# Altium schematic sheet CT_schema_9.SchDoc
size 297 x 239 mm
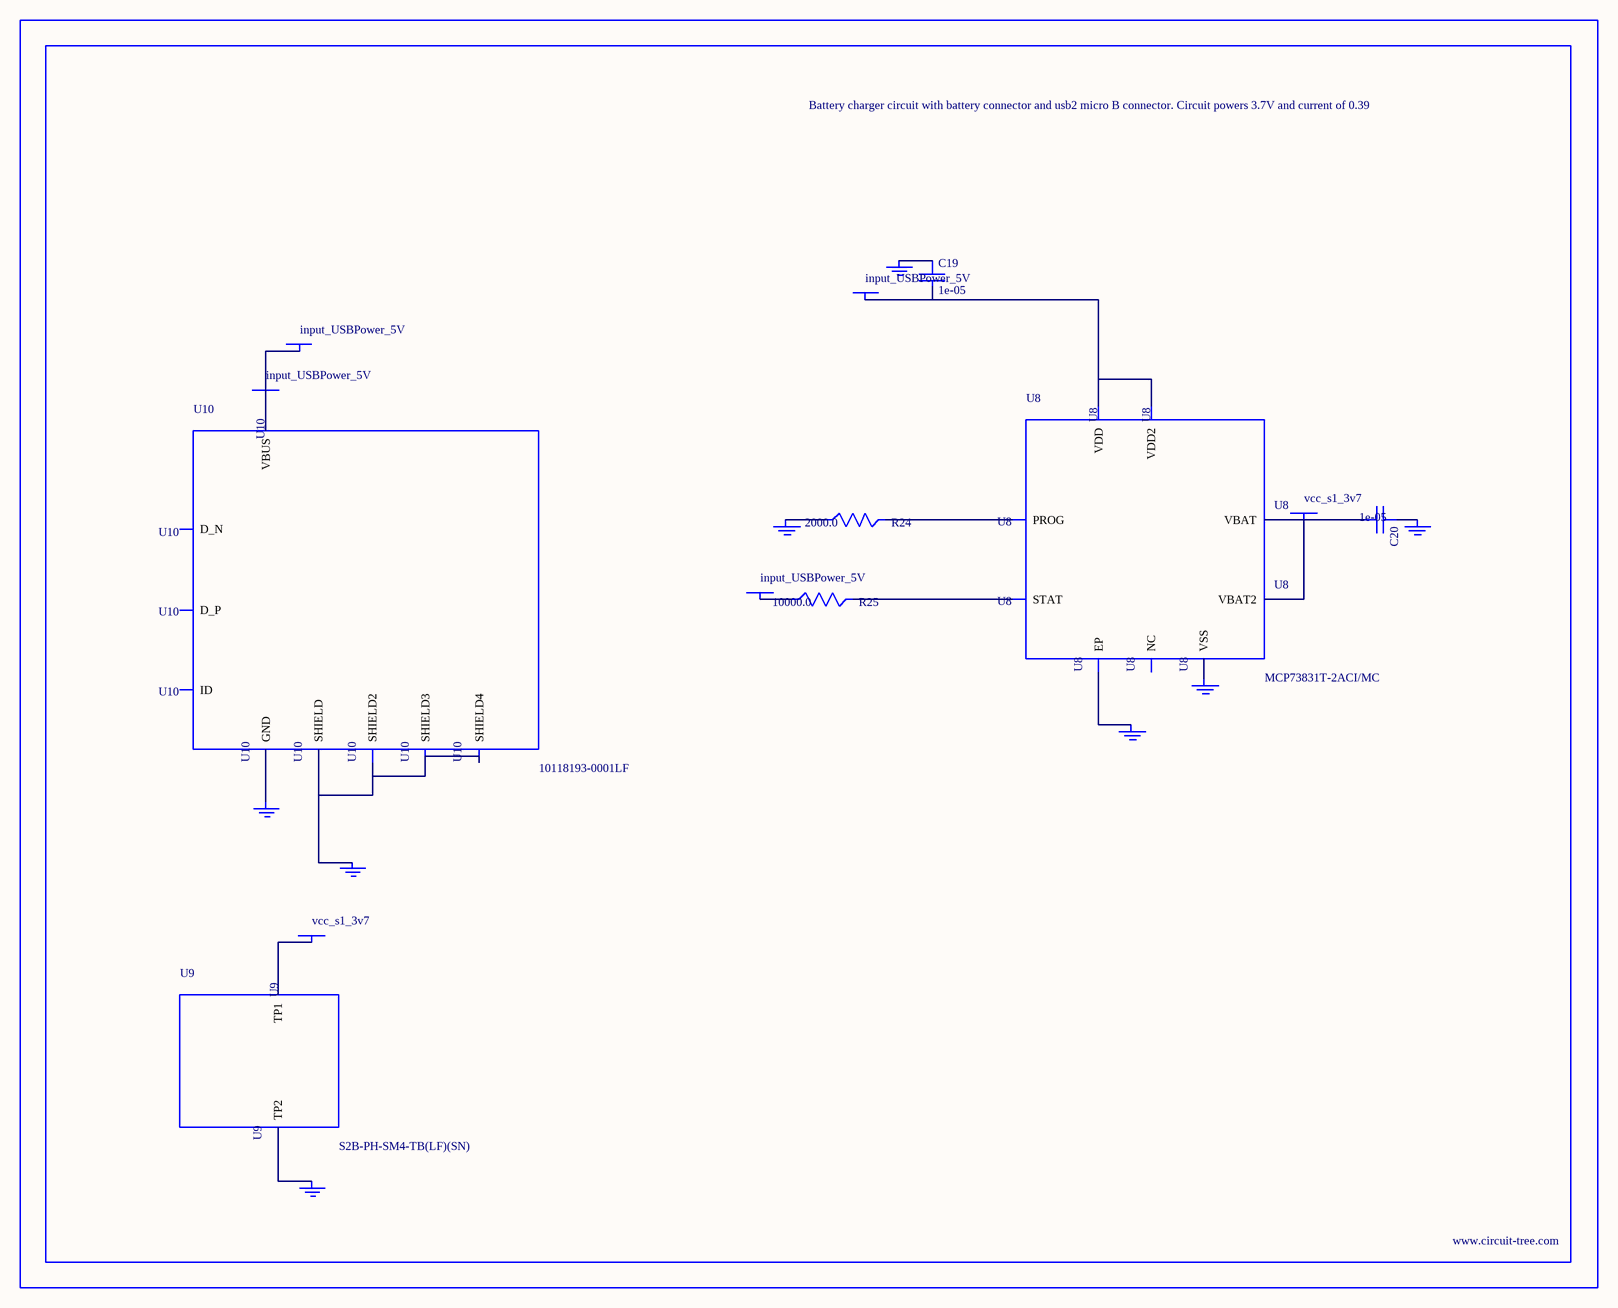
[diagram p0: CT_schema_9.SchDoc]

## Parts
BORDER8  (no value)
C19  1e-05  [C1206]
C20  1e-05  [C1206]
GND_INSTANCE_8_0  (no value)
GND_INSTANCE_8_1  (no value)
GND_INSTANCE_8_2  (no value)
GND_INSTANCE_8_3  (no value)
GND_INSTANCE_8_4  (no value)
GND_INSTANCE_8_5  (no value)
GND_INSTANCE_8_6  (no value)
GND_INSTANCE_8_7  (no value)
POWER_INSTANCE_8_0  input_USBPower_5V
POWER_INSTANCE_8_1  input_USBPower_5V
POWER_INSTANCE_8_2  vcc_s1_3v7
POWER_INSTANCE_8_3  vcc_s1_3v7
POWER_INSTANCE_8_4  input_USBPower_5V
POWER_INSTANCE_8_5  input_USBPower_5V
R24  2000.0  [R0603]
R25  10000.0  [R0603]
U8  MCP73831T-2ACI/MC  [DFN8_2X3MC]
U9  S2B-PH-SM4-TB(LF)(SN)  [JST-2-SMD]
U10  10118193-0001LF  [FCI_10118193-0001LF]

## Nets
NetC19_1: C19.1 GND_INSTANCE_8_0.0(GND)
NetC19_2: C19.2 POWER_INSTANCE_8_0.0(PWR) U8.1(VDD) U8.2(VDD2)
NetC20_1: C20.1 GND_INSTANCE_8_1.0(GND)
NetC20_2: C20.2 POWER_INSTANCE_8_2.0(PWR) U8.3(VBAT) U8.4(VBAT2)
NetGND_INSTANCE_8_2_0: GND_INSTANCE_8_2.0(GND) R24.1
NetGND_INSTANCE_8_3_0: GND_INSTANCE_8_3.0(GND) U8.9(EP)
NetGND_INSTANCE_8_4_0: GND_INSTANCE_8_4.0(GND) U8.6(VSS)
NetGND_INSTANCE_8_5_0: GND_INSTANCE_8_5.0(GND) U9.2(TP2)
NetGND_INSTANCE_8_6_0: GND_INSTANCE_8_6.0(GND) U10.6(SHIELD) U10.7(SHIELD2) U10.8(SHIELD3) U10.9(SHIELD4)
NetGND_INSTANCE_8_7_0: GND_INSTANCE_8_7.0(GND) U10.5(GND)
NetPOWER_INSTANCE_8_1_0: POWER_INSTANCE_8_1.0(PWR) R25.1
NetPOWER_INSTANCE_8_3_0: POWER_INSTANCE_8_3.0(PWR) U9.1(TP1)
NetPOWER_INSTANCE_8_4_0: POWER_INSTANCE_8_4.0(PWR) POWER_INSTANCE_8_5.0(PWR) U10.1(VBUS)
NetR24_2: R24.2 U8.8(PROG)
NetR25_2: R25.2 U8.5(STAT)

Not connected (* = marked no-connect by the designer): U8 7(NC); U10 2(D_N) 3(D_P) 4(ID)

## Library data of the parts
BORDER8 = BORDER_PAGE8
C19 C20 = C1206C106K3RACTU
GND_INSTANCE_8_0-GND_INSTANCE_8_7 = GND
POWER_INSTANCE_8_0-POWER_INSTANCE_8_5 = PWR
R24 = RC0603JR-072KL
R25 = RC0603JR-0710KL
